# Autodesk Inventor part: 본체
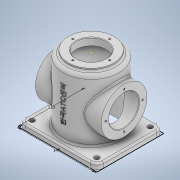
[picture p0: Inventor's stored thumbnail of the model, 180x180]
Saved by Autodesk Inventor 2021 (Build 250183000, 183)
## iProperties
Created: 2021-02
Part Number: 본체
Material: 알루미늄 6061
Document SubType Name: Modeling
Designer: mdu2-97
Density: 2.7 g/cm^3
Appearance: 기본값
Mass: 1251.31 g
Surface Area: 1080.97 cm^2
Volume: 463.448 cm^3
Author: mdu2-97
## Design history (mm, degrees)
sketch "스케치1"
  geometry: L1 (-70, -60)-(70, -60); L2 (70, -60)-(70, 60); L3 (70, 60)-(-70, 60); L4 (-70, 60)-(-70, -60); L5 (-70, -60)-(70, 60); L6 (70, -60)-(-70, 60); 1 further point
  constraints: 12 end point, 2 midpoint, 2 parallel, 1 horizontal, 1 perpendicular
  dimensions: "d0" = 140 distance of L3.end L2.end; "d1" = 120 distance of L2.end L1.end
extrude "돌출1" new body sketch "스케치1" distance "d2" = 10; taper "d3" = 0 deg
sketch "스케치2"
  geometry: 1 further point
sketch "스케치3"
  geometry: C1 r 50 at (0, 0); 1 further point
  constraints: 1 centre point, 1 coincident
  dimensions: "d4" = 100 diameter of C1
extrude "돌출2" join sketch "스케치3" distance "d5" = 110; taper "d6" = 0 deg
sketch "스케치6"
  geometry: 1 further point
sketch "스케치7"
  geometry: C1 r 27 at (0, 0); 1 further point
  constraints: 1 centre point, 1 coincident
  dimensions: "d12" = 54 diameter of C1
extrude "돌출4" cut sketch "스케치7" distance "d13" = 8; taper "d14" = 0 deg
sketch "스케치8"
  geometry: C1 r 42 at (0, 0); 1 further point
  constraints: 1 centre point, 1 coincident
  dimensions: "d15" = 84 diameter of C1
extrude "돌출5" cut sketch "스케치8" extent not by distance; stored distance "d16" = 0; taper "d17" = 0 deg
sketch "스케치9"
  geometry: C1 r 41 at (0, 0); 1 further point
  constraints: 1 centre point, 1 coincident
  dimensions: "d18" = 82 diameter of C1
extrude "돌출6" join sketch "스케치9" distance "d19" = 5; taper "d20" = 0 deg
sketch "스케치10"
  geometry: C1 r 27 at (0, 0) reference; 1 further point
extrude "돌출7" cut sketch "스케치10" extent not by distance; stored distance "d21" = 5; taper "d22" = 0 deg
fillet "모깎기1" dims "d23" = 6
fillet "모깎기2" dims "d24" = 3
node "작업 평면1"
sketch "스케치11"
  geometry: L1 (10, 60)-(10, -60) reference; L2 (125, -41)-(125, 41) reference; L3 (0, 60)-(0, -60) reference; L4 (10, 50)-(10, -50) reference; L5 (114, -50)-(114, 50) reference; L6 (114, 0)-(10, 0); C1 r 41 at (60, 0); 1 further point
  constraints: 2 end point, 2 midpoint, 1 centre point, 1 point on line
  dimensions: "d26" = 82 diameter of C1; "d27" = 60 distance from line of C1.centre L3
extrude "돌출8" join sketch "스케치11" stored distance "d28" = 5; taper "d29" = 0 deg
sketch "스케치12"
  geometry: C1 r 27 at (0, 0); C2 r 41 at (0, 0) reference; 1 further point
  constraints: 1 centre point, 1 coincident
  dimensions: "d30" = 54 diameter of C1
extrude "돌출9" cut sketch "스케치12" stored distance "d31" = 5; taper "d32" = 0 deg
fillet "모깎기3" dims "d33" = 3
sketch "스케치13"
  geometry: 1 further point
fillet "모깎기4" dims "d34" = 12
sketch "스케치14"
  geometry: C1 r 4.5 at (-58, -48); A1 r 12 centre (-58, -48) between (-70, -48) and (-58, -60) reference; A2 r 12 centre (-58, 48) between (-58, 60) and (-70, 48) reference; A3 r 12 centre (58, 48) between (70, 48) and (58, 60) reference; A4 r 12 centre (58, -48) between (58, -60) and (70, -48) reference; 1 further point
  constraints: 1 centre point, 1 coincident
  dimensions: "d35" = 9 diameter of C1
extrude "돌출10" cut sketch "스케치14" extent not by distance; stored distance "d36" = 0; taper "d37" = 0 deg
sketch "스케치15" dims "d38" = 66
  geometry: 3 further points
  constraints: 1 vertical alignment, 2 other
hole "구멍1" sketch "스케치15" at (0, 33) diameter "d39" = 3.242; stored, may be unused: countersink angle "d43" = 90 deg, drill point angle "d45" = 118 deg; dims "d40" = 8, "d41" = 12, "d42" = 2, "d44" = 10
sketch "스케치16" dims "d49" = 66
  geometry: 3 further points
  constraints: 1 coincident, 1 vertical alignment, 2 other
hole "구멍2" sketch "스케치16" at (0, 33) diameter "d50" = 3.242; stored, may be unused: countersink angle "d54" = 90 deg, drill point angle "d56" = 118 deg; dims "d51" = 8, "d52" = 12, "d53" = 2, "d55" = 10
fillet "모깎기5" dims "d60" = 3
chamfer "모따기1" distance "d61" = 1; stored, may be unused: second distance "d62" = 2, angle "d63" = 45 deg
sketch "스케치17"
  geometry: 1 further point
fillet "모깎기6" dims "d64" = 3
fillet "모깎기7" dims "d65" = 3
node "작업 평면3"
sketch "스케치18"
  geometry: L1 (-58, 0)-(58, 0) reference; L2 (0, 151.2)-(0, -25.2) reference; 2 further points
  constraints: 1 point on line, 1 other
  dimensions: "d67" = 66 distance from line of L1 point (0, 66)
feature "엠보싱1" sketch "스케치18" dims "d68" = 1, "d69" = 0
node "솔리드1"
mirror "미러1"
mirror "미러2"
mirror "미러3"
pattern_circular "원형 패턴1" dims angle "d47" = 360 deg
mirror "미러4"
pattern_circular "원형 패턴2" dims angle "d58" = 360 deg
node "투영된 루프1"
node "작업 평면2"
node "투영된 루프2"
feature "A9D066F2-1C7D-4E18-AEED-F7BC21143FA4" dims "d39" = 3.242, "d40" = 8, "d41" = 12, "d42" = 2, "d43" = 90 deg, "d44" = 10, "d45" = 118 deg
other parameters: "d25" = 59
